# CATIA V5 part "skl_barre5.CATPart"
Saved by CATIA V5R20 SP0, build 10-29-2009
Part number: skl_barre5
Publications: "Barre_5", "Axe_Pivot_b5b4", "Axe_Pivot_b5b6"
Bounding box of the stored display mesh (mm): x 234.923 to 234.923, y -218.208 to 201.792, z 0 to 20
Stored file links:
  C:\Users\Matthieu\Desktop\IFMA\Cours 2A\Thinkmotion\skl_barre5.CATPart
  C:\Users\Matthieu\Desktop\IFMA\Cours 2A\Thinkmotion\skl_IAO_bis.CATProduct
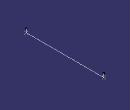
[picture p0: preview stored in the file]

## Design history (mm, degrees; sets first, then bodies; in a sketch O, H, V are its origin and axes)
AxisSystem1: origin (0, 0, 0), X (1, 0, 0), Y (0, 1, 0), Z (0, 0, 1)
Set1
  Point1 "Point.E": linked copy from another document
  Point2 "Point.F": linked copy from another document
  Plane1 "Plan_Ref": linked copy from another document
Body1 (main body)
  Line1 "Barre_5": type PtPt, FirstPoint Point1, SecondPoint Point2
  Line2 "Axe_Pivot_b5b4": type Normal, RefPoint Point1, RefSkin Plane1, Start 0, End 20
  Line3 "Axe_Pivot_b5b6": type Normal, RefPoint Point2, RefSkin Plane1, Start 0, End 20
